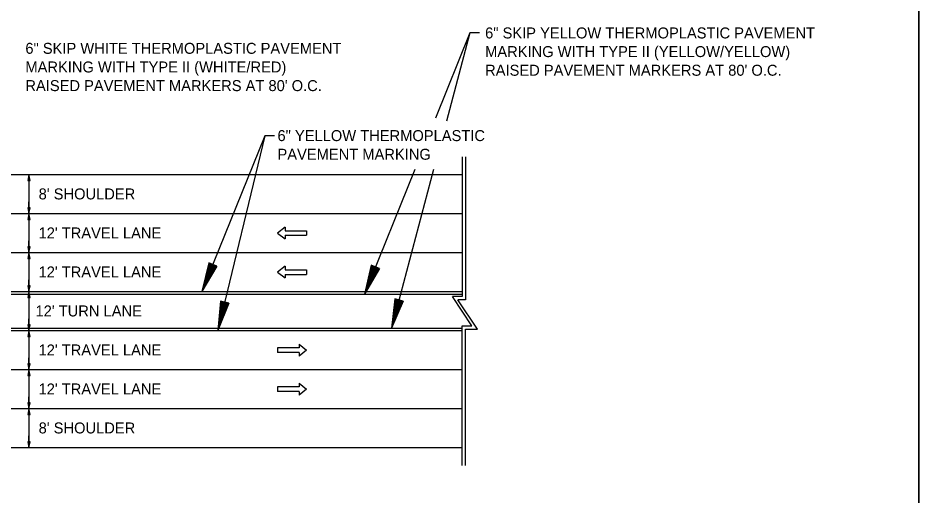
# Model space of a CAD drawing. Extents: x 1373096 to 1373266, y 381130 to 381790.
# Drawn here: x 1373173.6 to 1373266, y 381271.2 to 381320.2 of the extents above; entities that cross this region are included whole.
import ezdxf

# ---------------------------------------------------------------- set-up
doc = ezdxf.new("R2010")
doc.units = 0
for name, color, linetype in [('Default', 7, 'Continuous'), ('DSN_DRFT_Junk-No-Plot', 7, 'Continuous'), ('R_Draft', 7, 'Continuous')]:
    doc.layers.add(name, color=color, linetype=linetype)

msp = doc.modelspace()

# ---------------------------------------------------------------- linework, layer by layer
at = {"layer": 'Default'}
for p, q in [((1373219.95, 381318.656), (1373216.424, 381309.917)), ((1373219.95, 381318.656), (1373217.551, 381309.618)), ((1373220.95, 381318.656), (1373219.95, 381318.656)), ((1373198.936, 381308.092), (1373192.496, 381292.128)), ((1373198.936, 381308.092), (1373194.121, 381288.128)), ((1373199.936, 381308.092), (1373198.936, 381308.092)), ((1373219.169, 381305.965), (1373219.169, 381291.628)), ((1373219.502, 381305.965), (1373219.502, 381291.295)), ((1373214.305, 381304.664), (1373209.147, 381291.878)), ((1373216.238, 381304.671), (1373211.913, 381288.378)), ((1373201.021, 381298.728), (1373200.242, 381298.128)), ((1373201.021, 381298.728), (1373201.021, 381298.353)), ((1373200.242, 381298.128), (1373201.021, 381297.528)), ((1373201.021, 381298.353), (1373203.227, 381298.353)), ((1373201.021, 381297.903), (1373203.227, 381297.903)), ((1373201.021, 381297.903), (1373201.021, 381297.528)), ((1373203.227, 381298.353), (1373203.227, 381297.903)), ((1373193.201, 381295.078), (1373192.496, 381292.128)), ((1373193.271, 381295.05), (1373192.684, 381292.593)), ((1373193.342, 381295.022), (1373192.877, 381293.071)), ((1373194.036, 381294.742), (1373193.201, 381295.078)), ((1373194.036, 381294.742), (1373192.496, 381292.128)), ((1373193.966, 381294.77), (1373192.684, 381292.593)), ((1373193.895, 381294.798), (1373192.877, 381293.071)), ((1373193.411, 381294.994), (1373193.064, 381293.534)), ((1373193.826, 381294.826), (1373193.064, 381293.534)), ((1373193.482, 381294.965), (1373193.254, 381294.006)), ((1373193.754, 381294.856), (1373193.254, 381294.006)), ((1373193.553, 381294.936), (1373193.441, 381294.47)), ((1373193.684, 381294.884), (1373193.441, 381294.47)), ((1373201.021, 381294.728), (1373200.242, 381294.128)), ((1373200.242, 381294.128), (1373201.021, 381293.528)), ((1373201.021, 381294.728), (1373201.021, 381294.353)), ((1373201.021, 381294.353), (1373203.227, 381294.353)), ((1373203.227, 381294.353), (1373203.227, 381293.903)), ((1373209.852, 381294.828), (1373209.147, 381291.878)), ((1373210.687, 381294.492), (1373209.147, 381291.878)), ((1373209.922, 381294.8), (1373209.334, 381292.343)), ((1373210.617, 381294.52), (1373209.334, 381292.343)), ((1373209.993, 381294.772), (1373209.528, 381292.821)), ((1373210.546, 381294.548), (1373209.528, 381292.821)), ((1373210.062, 381294.744), (1373209.714, 381293.284)), ((1373210.477, 381294.576), (1373209.714, 381293.284)), ((1373210.687, 381294.492), (1373209.852, 381294.828)), ((1373210.133, 381294.715), (1373209.905, 381293.756)), ((1373210.404, 381294.606), (1373209.905, 381293.756)), ((1373210.204, 381294.686), (1373210.092, 381294.22)), ((1373210.335, 381294.634), (1373210.092, 381294.22)), ((1373201.021, 381293.903), (1373203.227, 381293.903)), ((1373201.021, 381293.903), (1373201.021, 381293.528)), ((1373212.248, 381291.393), (1373211.913, 381288.378)), ((1373212.32, 381291.374), (1373212.042, 381288.862)), ((1373212.394, 381291.354), (1373212.174, 381289.361)), ((1373213.118, 381291.162), (1373212.248, 381291.393)), ((1373212.467, 381291.335), (1373212.302, 381289.844)), ((1373219.169, 381291.628), (1373218.169, 381291.628)), ((1373220.169, 381288.628), (1373218.169, 381291.628)), ((1373194.387, 381291.15), (1373194.121, 381288.128)), ((1373195.262, 381290.939), (1373194.121, 381288.128)), ((1373194.46, 381291.132), (1373194.239, 381288.615)), ((1373195.189, 381290.956), (1373194.239, 381288.615)), ((1373194.535, 381291.114), (1373194.36, 381289.117)), ((1373195.115, 381290.974), (1373194.36, 381289.117)), ((1373195.262, 381290.939), (1373194.387, 381291.15)), ((1373194.608, 381291.097), (1373194.477, 381289.602)), ((1373195.042, 381290.992), (1373194.477, 381289.602)), ((1373194.682, 381291.079), (1373194.596, 381290.096)), ((1373194.966, 381291.01), (1373194.596, 381290.096)), ((1373194.756, 381291.061), (1373194.714, 381290.583)), ((1373194.893, 381291.028), (1373194.714, 381290.583)), ((1373213.118, 381291.162), (1373211.913, 381288.378)), ((1373213.045, 381291.181), (1373212.042, 381288.862)), ((1373212.971, 381291.201), (1373212.174, 381289.361)), ((1373212.899, 381291.22), (1373212.302, 381289.844)), ((1373212.541, 381291.315), (1373212.433, 381290.335)), ((1373212.823, 381291.24), (1373212.433, 381290.335)), ((1373212.615, 381291.296), (1373212.561, 381290.819)), ((1373212.751, 381291.259), (1373212.561, 381290.819)), ((1373220.725, 381288.295), (1373218.725, 381291.295)), ((1373219.502, 381291.295), (1373218.725, 381291.295)), ((1373219.169, 381274.291), (1373219.169, 381288.628)), ((1373219.169, 381288.628), (1373220.169, 381288.628)), ((1373219.502, 381274.291), (1373219.502, 381288.295)), ((1373219.502, 381288.295), (1373220.725, 381288.295)), ((1373202.449, 381286.728), (1373202.449, 381286.353)), ((1373202.449, 381286.728), (1373203.227, 381286.128)), ((1373202.449, 381286.353), (1373200.242, 381286.353)), ((1373200.242, 381286.353), (1373200.242, 381285.903)), ((1373202.449, 381285.903), (1373200.242, 381285.903)), ((1373203.227, 381286.128), (1373202.449, 381285.528)), ((1373202.449, 381285.903), (1373202.449, 381285.528)), ((1373202.449, 381282.353), (1373200.242, 381282.353)), ((1373200.242, 381282.353), (1373200.242, 381281.903)), ((1373202.449, 381282.728), (1373202.449, 381282.353)), ((1373202.449, 381282.728), (1373203.227, 381282.128)), ((1373203.227, 381282.128), (1373202.449, 381281.528)), ((1373202.449, 381281.903), (1373200.242, 381281.903)), ((1373202.449, 381281.903), (1373202.449, 381281.528))]:
    msp.add_line(p, q, dxfattribs=at)
msp.add_lwpolyline([(1373095.974, 381350.174), (1373095.974, 381240.174), (1373265.974, 381240.174), (1373265.974, 381350.174)], close=True, dxfattribs=at)
at = {"layer": 'DSN_DRFT_Junk-No-Plot'}
msp.add_line((1373174.763, 381304.128), (1373174.763, 381276.128), dxfattribs=at)
for points in [[(1373095.974, 381350.174), (1373265.974, 381350.174), (1373265.974, 381240.174), (1373095.974, 381240.174)], [(1373095.974, 381350.174), (1373095.974, 381240.174), (1373265.974, 381240.174), (1373265.974, 381350.174)]]:
    msp.add_lwpolyline(points, close=True, dxfattribs=at)
for points in [[(1373174.763, 381304.128), (1373174.643, 381303.528), (1373174.883, 381303.528), (1373174.763, 381304.128), (1373174.763, 381302.928)], [(1373174.763, 381300.128), (1373174.883, 381300.728), (1373174.643, 381300.728), (1373174.763, 381300.128), (1373174.763, 381301.328)], [(1373174.763, 381300.128), (1373174.643, 381299.528), (1373174.883, 381299.528), (1373174.763, 381300.128), (1373174.763, 381298.928)], [(1373174.763, 381296.128), (1373174.883, 381296.728), (1373174.643, 381296.728), (1373174.763, 381296.128), (1373174.763, 381297.328)], [(1373174.763, 381296.128), (1373174.643, 381295.528), (1373174.883, 381295.528), (1373174.763, 381296.128), (1373174.763, 381294.928)], [(1373174.763, 381292.128), (1373174.883, 381292.728), (1373174.643, 381292.728), (1373174.763, 381292.128), (1373174.763, 381293.328)], [(1373174.763, 381292.128), (1373174.643, 381291.528), (1373174.883, 381291.528), (1373174.763, 381292.128), (1373174.763, 381290.928)], [(1373174.763, 381288.128), (1373174.883, 381288.728), (1373174.643, 381288.728), (1373174.763, 381288.128), (1373174.763, 381289.328)], [(1373174.763, 381288.128), (1373174.643, 381287.528), (1373174.883, 381287.528), (1373174.763, 381288.128), (1373174.763, 381286.928)], [(1373174.763, 381284.128), (1373174.883, 381284.728), (1373174.643, 381284.728), (1373174.763, 381284.128), (1373174.763, 381285.328)], [(1373174.763, 381284.128), (1373174.643, 381283.528), (1373174.883, 381283.528), (1373174.763, 381284.128), (1373174.763, 381282.928)], [(1373174.763, 381280.128), (1373174.883, 381280.728), (1373174.643, 381280.728), (1373174.763, 381280.128), (1373174.763, 381281.328)], [(1373174.763, 381280.128), (1373174.643, 381279.528), (1373174.883, 381279.528), (1373174.763, 381280.128), (1373174.763, 381278.928)], [(1373174.763, 381276.128), (1373174.883, 381276.728), (1373174.643, 381276.728), (1373174.763, 381276.128), (1373174.763, 381277.328)]]:
    msp.add_lwpolyline(points, dxfattribs=at)
at = {"layer": 'R_Draft'}
for p, q in [((1373142.778, 381304.128), (1373219.169, 381304.128)), ((1373142.778, 381300.128), (1373219.169, 381300.128)), ((1373142.778, 381296.128), (1373219.169, 381296.128)), ((1373142.778, 381292.128), (1373219.169, 381292.128)), ((1373142.778, 381291.878), (1373219.169, 381291.878)), ((1373142.778, 381288.378), (1373219.169, 381288.378)), ((1373142.778, 381288.128), (1373219.169, 381288.128)), ((1373142.778, 381284.128), (1373219.169, 381284.128)), ((1373142.778, 381280.128), (1373219.169, 381280.128)), ((1373142.778, 381276.128), (1373219.169, 381276.128))]:
    msp.add_line(p, q, dxfattribs=at)

# ---------------------------------------------------------------- texts
at = {"layer": 'Default'}
for s, p in [('6" SKIP YELLOW THERMOPLASTIC PAVEMENT', (1373221.513, 381318.094)), ('6" SKIP WHITE THERMOPLASTIC PAVEMENT', (1373174.403, 381316.517)), ('MARKING WITH TYPE II (YELLOW/YELLOW)', (1373221.513, 381316.181)), ('MARKING WITH TYPE II (WHITE/RED)', (1373174.403, 381314.605)), ("RAISED PAVEMENT MARKERS AT 80' O.C.", (1373221.513, 381314.269)), ("RAISED PAVEMENT MARKERS AT 80' O.C.", (1373174.403, 381312.693)), ('6" YELLOW THERMOPLASTIC', (1373200.237, 381307.566)), ('PAVEMENT MARKING', (1373200.237, 381305.653))]:
    msp.add_text(s, height=1.125, dxfattribs=at).set_placement(p)
at = {"layer": 'R_Draft'}
for s, p in [("8' SHOULDER", (1373175.762, 381301.586)), ("12' TRAVEL LANE", (1373175.752, 381297.586)), ("12' TRAVEL LANE", (1373175.752, 381293.586)), ("12' TURN LANE", (1373175.441, 381289.586)), ("12' TRAVEL LANE", (1373175.752, 381285.586)), ("12' TRAVEL LANE", (1373175.752, 381281.586)), ("8' SHOULDER", (1373175.762, 381277.586))]:
    msp.add_text(s, height=1.125, dxfattribs=at).set_placement(p)

doc.saveas('drawing.dxf')
